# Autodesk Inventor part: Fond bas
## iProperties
Author: Flavien MARTY
Shininess: 20.0
PropertySet Name: _Private Model Information
Created: 2001-10
Part Number: Fond bas
Material: Par défaut
Document SubType Name: Modélisation
Designer: Flavien MARTY
Control State: 0
Master: False
Checked Out: False
PropertySet Name: Design Tracking Control
Density: 0.0
Volumn: 0.0
Area: 0.0
PropertySet Name: Model Information
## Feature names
1. Base1
